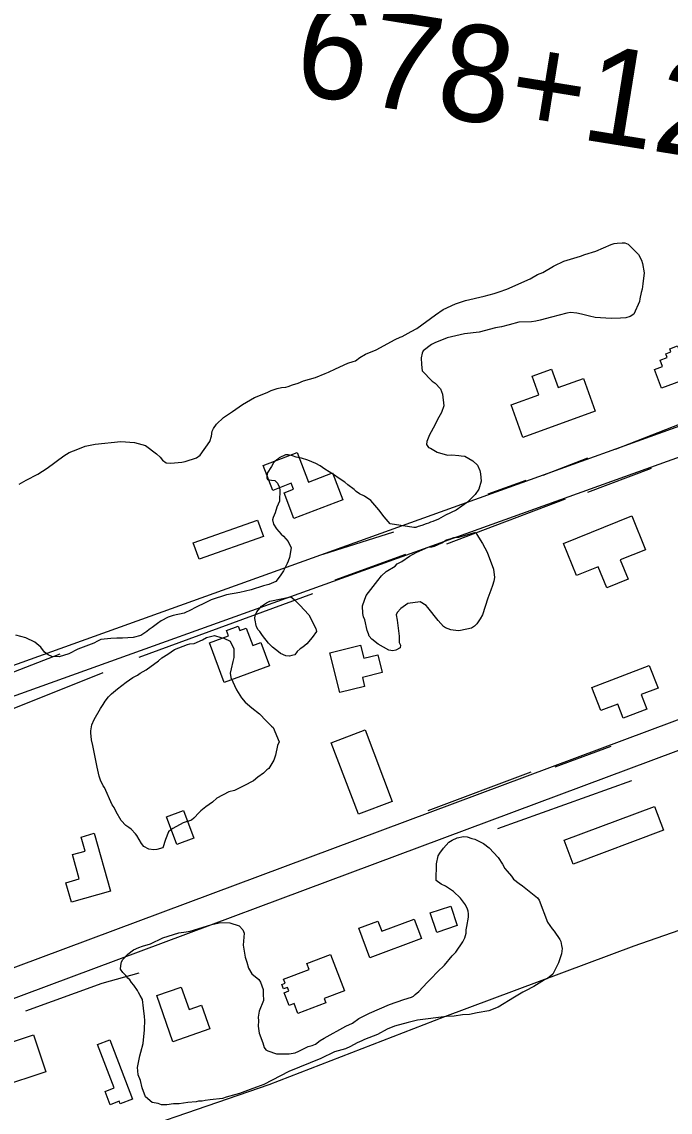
# Model space of a CAD drawing. Extents: x 3161564 to 3199464, y 849354 to 874788.
# Drawn here: x 3173329 to 3173999, y 861534 to 862661 of the extents above; entities that cross this region are included whole.
import ezdxf

# ---------------------------------------------------------------- set-up
doc = ezdxf.new("R2010")
doc.units = 0
for name, color, linetype in [('V-BLDG-OTLN', 7, 'Continuous'), ('V-ROAD-CNTR', 7, 'Continuous'), ('V-SITE-VEGE', 7, 'Continuous'), ('V-SURV-IDEN', 7, 'Continuous'), ('V-TOPO-SHOR', 7, 'Continuous')]:
    doc.layers.add(name, color=color, linetype=linetype)

msp = doc.modelspace()

# ---------------------------------------------------------------- linework, layer by layer
at = {"layer": 'V-BLDG-OTLN'}
for points in [[(3173989.6, 862281.9), (3173982.5, 862301.3), (3173990.6, 862304.3), (3173988.2, 862310.9), (3173995.6, 862313.6), (3173994.2, 862317.5), (3173999.5, 862319.5), (3173998.3, 862322.6), (3174006.3, 862325.6), (3174009.2, 862318), (3174044.6, 862331.1), (3174054, 862305.8)], [(3173834.3, 862264.7), (3173863, 862275.1), (3173856, 862294.3), (3173876.1, 862301.6), (3173883, 862282.7), (3173909, 862292.1), (3173921.2, 862258.3), (3173846.5, 862231.1)], [(3173609.9, 862147.2), (3173599.8, 862173.6), (3173609.7, 862177.4), (3173607.3, 862183.7), (3173588.1, 862176.3), (3173578.3, 862201.9), (3173613.4, 862215.4), (3173625.2, 862184.9), (3173649.7, 862194.4), (3173660.4, 862166.6)], [(3173902, 862088.2), (3173888.5, 862121.4), (3173959, 862150.1), (3173973.3, 862115), (3173947.2, 862104.4), (3173955.3, 862084.4), (3173933.2, 862075.4), (3173924.3, 862097.3)], [(3173572.5, 862145.6), (3173578.5, 862128.6), (3173512.1, 862105.2), (3173506.1, 862122.2)], [(3173537.8, 861977.7), (3173522.7, 862018.8), (3173542.3, 862026.1), (3173540.2, 862031.6), (3173552.3, 862036.1), (3173554, 862031.5), (3173560.7, 862033.9), (3173567.4, 862015.8), (3173575.9, 862018.9), (3173584.7, 861995)], [(3173657.5, 861967.3), (3173647.1, 862008.3), (3173678.9, 862016.4), (3173682.3, 862002.8), (3173696.6, 862006.4), (3173701.3, 861988), (3173680.7, 861982.8), (3173683, 861973.7)], [(3173927.1, 861948.7), (3173917.9, 861972.7), (3173977.1, 861995.4), (3173986.2, 861971.8), (3173968.9, 861965.2), (3173974.7, 861950), (3173950.2, 861940.7), (3173944.5, 861955.4)], [(3173676.6, 861841.5), (3173648.6, 861915.5), (3173683.7, 861928.7), (3173711.6, 861854.7)], [(3173489.1, 861810.3), (3173478.5, 861839), (3173496.1, 861845.5), (3173506.7, 861816.8)], [(3173898.4, 861789.9), (3173889.1, 861814.6), (3173982.6, 861849.6), (3173991.9, 861824.9)], [(3173380.1, 861750.8), (3173374.5, 861770.8), (3173388.2, 861774.6), (3173381.3, 861799.8), (3173394.2, 861803.4), (3173390.2, 861818), (3173403.8, 861821.8), (3173420.4, 861762)], [(3173750.9, 861739.5), (3173772, 861746.5), (3173778.7, 861726.4), (3173757.6, 861719.4)], [(3173688.4, 861693.1), (3173676.9, 861723.6), (3173696.8, 861731), (3173700.7, 861720.5), (3173734.3, 861733.1), (3173741.8, 861713.2)], [(3173599.3, 861671), (3173625.6, 861681), (3173623.2, 861687.2), (3173647.7, 861696.5), (3173662.1, 861658.9), (3173641.4, 861651), (3173643.1, 861646.6), (3173614, 861635.5), (3173610.1, 861645.8), (3173605, 861643.8), (3173599.9, 861657), (3173604.8, 861658.9), (3173603.4, 861662.6), (3173599.3, 861661), (3173597.5, 861665.6), (3173600.9, 861666.9)], [(3173468.3, 861654), (3173493.6, 861662.8), (3173501.7, 861639.6), (3173514.6, 861644.1), (3173523.2, 861619.6), (3173484.9, 861606.2)], [(3173305.6, 861559.3), (3173292.8, 861597.5), (3173341, 861613.6), (3173353.8, 861575.4)], [(3173419.8, 861608.4), (3173443.3, 861547), (3173430.5, 861542.1), (3173429.5, 861544.9), (3173420.2, 861541.3), (3173414.9, 861555), (3173424.2, 861558.6), (3173407.1, 861603.6)]]:
    msp.add_lwpolyline(points, close=True, dxfattribs=at)
at = {"layer": 'V-ROAD-CNTR'}
for points in [[(3174370.7, 862373), (3172595.4, 861734.8)], [(3174380.8, 862344.8), (3172605.6, 861706.6)], [(3172696.1, 861449.9), (3174403, 862087.4)], [(3172706.5, 861421.8), (3174413.5, 862059.3)]]:
    msp.add_lwpolyline(points, dxfattribs=at)
at = {"layer": 'V-SITE-VEGE'}
for points in [[(3173345.3, 862192.9), (3173355.1, 862199.4), (3173372.3, 862212.1), (3173378, 862215.4), (3173386.9, 862218.9), (3173394.4, 862222.1), (3173404.8, 862224.2), (3173431.2, 862226.7), (3173445.3, 862225.7), (3173456.7, 862222.6), (3173468.1, 862214.2), (3173471.7, 862210.5), (3173474.3, 862207.5), (3173477.9, 862204.8), (3173482.7, 862204.3), (3173494.3, 862205.6), (3173497.6, 862206.3), (3173509.5, 862209.8), (3173513.3, 862212.7), (3173523.2, 862226.7), (3173524.8, 862232.2), (3173525.6, 862237.4), (3173527.1, 862240.3), (3173530.2, 862244.7), (3173537.3, 862251.7), (3173546.7, 862257.8), (3173550.1, 862260.3), (3173556.8, 862265.1), (3173569.2, 862272.3), (3173575.5, 862274.8), (3173583, 862278), (3173586.4, 862279.4), (3173592.7, 862281.5), (3173597.2, 862282.6), (3173601.6, 862282.9), (3173604.2, 862283.6), (3173608.7, 862285.3), (3173614.3, 862287.1), (3173619.9, 862289.6), (3173632.2, 862293.1), (3173642.3, 862297), (3173645.7, 862298.4), (3173653.1, 862302), (3173665.8, 862307.8), (3173671.1, 862309.5), (3173673.7, 862310.2), (3173678.2, 862313.8), (3173683.8, 862317.1), (3173695, 862321.7), (3173714.5, 862332.2), (3173719.7, 862334.7), (3173721.9, 862335.4), (3173731.3, 862340.4), (3173736.9, 862343.7), (3173756.1, 862357.8), (3173764.3, 862363.2), (3173777, 862369), (3173787.1, 862372.5), (3173806.5, 862377), (3173816.9, 862379.8), (3173822.1, 862381.6), (3173829.9, 862384.4), (3173854.2, 862395.1), (3173861.7, 862399.4), (3173867.3, 862401.6), (3173878.2, 862408.1), (3173881.6, 862409.9), (3173886, 862411.7), (3173888.7, 862413.1), (3173906.2, 862418.4), (3173910.7, 862420.1), (3173921.8, 862423.7), (3173929.7, 862426.9), (3173937.9, 862430.5), (3173940.9, 862431.5), (3173943.9, 862431.8), (3173949.1, 862432.1), (3173952, 862432.1), (3173955.3, 862430.9)], [(3173955.3, 862430.9), (3173965.9, 862420), (3173969.2, 862414.4), (3173970.2, 862411), (3173971.9, 862401.3), (3173970.6, 862389.8), (3173969.8, 862384.3), (3173968.6, 862381), (3173967.4, 862374.3), (3173967, 862371.4), (3173961.2, 862358.5), (3173957.4, 862355.9), (3173953, 862354.5), (3173947.4, 862354.3), (3173937.7, 862354), (3173921.1, 862355.1), (3173915.5, 862356.3), (3173907, 862358.6), (3173902.2, 862359.5), (3173895.9, 862360.3), (3173891.8, 862359.6), (3173876.2, 862355.4), (3173864.3, 862352.3), (3173859.8, 862351.3), (3173855.3, 862350.6), (3173842.4, 862350.1), (3173832.3, 862347.6), (3173824.5, 862345.5), (3173818.1, 862344.2), (3173801.4, 862340), (3173786.1, 862338), (3173768.3, 862333.9), (3173755.6, 862328.9), (3173752.2, 862327.1), (3173743.6, 862320.6), (3173742.4, 862318), (3173741.6, 862313.2), (3173741.9, 862306.5), (3173742.5, 862299.8), (3173752.7, 862289.2), (3173756, 862287), (3173761.5, 862281.3), (3173763.6, 862275.7), (3173764.9, 862263.8), (3173762.5, 862256.8), (3173758.3, 862249.5), (3173755.6, 862243.6), (3173749.9, 862233.7), (3173747.2, 862226.7), (3173746.8, 862223.7), (3173749, 862220.7), (3173751.2, 862219.9), (3173758.1, 862215.7), (3173768.5, 862212.6), (3173773.3, 862212.9), (3173780.4, 862212.4), (3173782.9, 862212), (3173786.6, 862211.5), (3173794.7, 862206.9), (3173799.8, 862202.4), (3173802, 862196.8), (3173802.7, 862193.5), (3173803.6, 862186), (3173800.9, 862177.5), (3173797.1, 862172), (3173794.8, 862169.5), (3173789.2, 862164), (3173777.6, 862156), (3173766.7, 862150.7), (3173759.2, 862146.7), (3173753.6, 862144.2), (3173751, 862143.5), (3173749.1, 862142.4), (3173746.5, 862141.7), (3173742.1, 862139.9), (3173738.3, 862138.9), (3173736.1, 862137.8), (3173733.9, 862137.9), (3173709.4, 862141.6), (3173703.3, 862148.8), (3173697.8, 862156.3), (3173689.4, 862165.7), (3173682.8, 862170.2), (3173677.7, 862172.9), (3173674.4, 862175.2), (3173672.2, 862177.1), (3173665.6, 862182), (3173662.7, 862184.7), (3173656.8, 862188.5), (3173650.9, 862192.6), (3173641.8, 862198.4), (3173637, 862201.8), (3173632.6, 862204.1), (3173624.5, 862207.6), (3173617.8, 862209.5), (3173612.3, 862210.7), (3173608.6, 862211.9), (3173604.2, 862213.1), (3173601.2, 862213.1), (3173594.9, 862209.9), (3173593.3, 862208.4)], [(3173593.3, 862208.4), (3173590.7, 862206.6), (3173588.8, 862204.8), (3173586.9, 862201.1), (3173582.4, 862194.2), (3173581.9, 862189.3), (3173582.6, 862187.5), (3173586.7, 862186.7), (3173590.4, 862186.6), (3173592.9, 862183.6), (3173594.7, 862179.9), (3173595.4, 862176.9), (3173595.2, 862165), (3173593.7, 862162.1), (3173592.5, 862159.1), (3173590.6, 862153.2), (3173588.6, 862148.4), (3173587.9, 862145.8), (3173588.9, 862141.4), (3173592.1, 862136.5), (3173596.9, 862130.9), (3173599.4, 862129), (3173604.2, 862123.3), (3173607, 862117), (3173605.4, 862107), (3173604.2, 862103.3), (3173603.1, 862100.7), (3173599.2, 862093), (3173596.6, 862089), (3173593.9, 862085.3), (3173591.2, 862082), (3173584.1, 862079.1), (3173578.6, 862077.8), (3173565.9, 862073.5), (3173554, 862070.7), (3173540.2, 862068.4), (3173524.5, 862063.1), (3173519.7, 862060.6), (3173507.7, 862054.8), (3173504, 862052.7), (3173496.5, 862049.4), (3173485.3, 862047), (3173480.1, 862045.3), (3173473, 862041.3), (3173469.2, 862038.8), (3173463.6, 862034.4), (3173460.6, 862032.6), (3173458, 862030.4), (3173452, 862026.4), (3173443.8, 862024.4), (3173433, 862023.4), (3173427.1, 862023.5), (3173420.8, 862023.3), (3173410.7, 862022.3), (3173407, 862020.5), (3173403.3, 862018.4), (3173386.8, 862012), (3173377.5, 862007.3), (3173367.4, 862004.1), (3173360, 862004.6), (3173356.3, 862006.2), (3173352.3, 862009.2), (3173348.7, 862014.1), (3173342.4, 862019.4), (3173332.9, 862024), (3173322.9, 862026.7)], [(3173326.2, 862182.8), (3173333.4, 862186.8), (3173345.3, 862192.9)], [(3173558.5, 861718.7), (3173557.6, 861706.1), (3173559.6, 861693.8), (3173561.3, 861688.6), (3173563.1, 861682.3), (3173566.7, 861676.6), (3173573.6, 861670.6), (3173575.5, 861668), (3173578.3, 861660.5), (3173578.2, 861656), (3173578.5, 861649), (3173574.2, 861637.9), (3173573, 861631.6), (3173573.3, 861627.9), (3173573.2, 861622.4), (3173574.2, 861615.3), (3173577.8, 861605.2), (3173579.2, 861600.4), (3173581, 861598.1), (3173583.2, 861597), (3173592, 861593.9), (3173605, 861593.7), (3173611.3, 861595), (3173615.1, 861596.5), (3173624.8, 861601.5), (3173628.9, 861602.5), (3173632.3, 861604), (3173637.1, 861607.6), (3173641.3, 861610.1), (3173663.7, 861622.4), (3173670.5, 861625.6), (3173677.2, 861630.3), (3173688.1, 861636), (3173708.6, 861645), (3173723.5, 861649.9), (3173731.4, 861652.4), (3173733.6, 861653.5), (3173735.1, 861655.3), (3173738.9, 861658.2), (3173747.6, 861667.7), (3173751.7, 861671.7), (3173758.5, 861678.6), (3173765.7, 861685.6), (3173773.6, 861695.1), (3173777.4, 861699.1), (3173784.6, 861709.7), (3173786.5, 861713.8), (3173788.1, 861718.6), (3173788.1, 861721.9), (3173788.6, 861725.6), (3173790.2, 861735.2), (3173790.3, 861738.6), (3173789.9, 861741.2), (3173789.2, 861743.4), (3173787.1, 861747.9), (3173785.3, 861750.5), (3173782, 861754.7), (3173774.7, 861761.5), (3173766.6, 861767.2), (3173762.2, 861769.4), (3173757.1, 861772.9), (3173757.4, 861790.3), (3173759, 861798.4), (3173760.9, 861801.4), (3173764.7, 861806.5), (3173770, 861812.7), (3173773.4, 861814.9), (3173778.6, 861817), (3173785.3, 861818.4), (3173789, 861818.3), (3173793.8, 861816.4), (3173796.8, 861815.6), (3173806, 861811.4), (3173811.8, 861806.8), (3173820.9, 861796.7), (3173825.6, 861789.9), (3173827.8, 861785.4), (3173830.3, 861782.8), (3173834.7, 861777.5), (3173836.9, 861774.5), (3173842.7, 861770), (3173846, 861767.7), (3173861.8, 861755.2)], [(3173861.8, 861755.2), (3173863.2, 861752.6), (3173872.1, 861729.8), (3173876.8, 861723), (3173879, 861720.8), (3173884.8, 861712.1), (3173885.9, 861709.9), (3173886.5, 861705.8), (3173887.2, 861702.8), (3173886.4, 861697.3), (3173883.3, 861688.1), (3173881.7, 861684.4), (3173877.5, 861676.3), (3173871.9, 861671.9), (3173868.9, 861670.5), (3173858, 861663.6), (3173849.4, 861659), (3173846.4, 861657.5), (3173837.8, 861652.5), (3173820.9, 861642), (3173811.2, 861638.4), (3173799.3, 861636.4), (3173791.5, 861634.7), (3173784.1, 861634.1), (3173775.5, 861632.7), (3173767.7, 861632.5), (3173737.6, 861628.5), (3173728, 861626.1), (3173713.8, 861622.3), (3173706.3, 861619.4), (3173696.2, 861614), (3173682.8, 861608.7), (3173680.2, 861607.2), (3173675.3, 861605.1), (3173668.6, 861601.5), (3173663.3, 861599), (3173651.8, 861595.8), (3173637.9, 861589), (3173604.7, 861575.5), (3173578.9, 861562.2), (3173567.7, 861557.9), (3173553.9, 861553), (3173540.1, 861549.1), (3173536.4, 861547.7), (3173523.4, 861546.4), (3173518.2, 861545.8), (3173515.2, 861545.1), (3173511.5, 861544.8), (3173508.9, 861544.1), (3173500.3, 861543.5), (3173491.4, 861542.1), (3173485.5, 861542.2), (3173478.8, 861541.2), (3173473.2, 861541.3), (3173469.9, 861542.5), (3173463.6, 861543.7), (3173456.7, 861549.4), (3173453.1, 861558.7), (3173451.4, 861566.2), (3173449.2, 861572.1), (3173448.6, 861576.2), (3173448.3, 861579.9), (3173449.9, 861586.6), (3173450.7, 861591.8), (3173451.9, 861595.5), (3173454.2, 861604.7), (3173455.6, 861618.8), (3173455.6, 861621.7), (3173456.1, 861625.8), (3173456.1, 861628.4), (3173455.8, 861632.5), (3173454.5, 861641), (3173453.5, 861650), (3173451.3, 861654.1), (3173449.5, 861657.1), (3173448.5, 861659.3), (3173444.5, 861664.9), (3173442.3, 861667.6), (3173440.5, 861670.2), (3173438.3, 861672.1), (3173436.5, 861674.7), (3173433.2, 861678.1), (3173431, 861681.5), (3173431.1, 861685.2), (3173431.9, 861688.9), (3173433.1, 861691.5), (3173438.3, 861696.9), (3173444.3, 861701.3), (3173449.9, 861703.8), (3173453.7, 861705.2), (3173461.9, 861707.7), (3173474.6, 861713.8), (3173491, 861719.1), (3173498.8, 861720), (3173502.9, 861720.7), (3173525.3, 861727.4), (3173534.6, 861729.5), (3173543.8, 861729.3), (3173553.4, 861726.2), (3173557.1, 861722), (3173558.5, 861718.7)]]:
    msp.add_lwpolyline(points, dxfattribs=at)
for points in [[(3173797.9, 862133.1), (3173799, 862130.8), (3173804.8, 862121.5), (3173809.8, 862112.5), (3173816.2, 862094.9), (3173817.2, 862086.4), (3173816.4, 862082.3), (3173815.2, 862077.9), (3173813.3, 862073.1), (3173810.5, 862065), (3173804.7, 862047.7), (3173802.4, 862043.6), (3173799, 862038.5), (3173796.7, 862035.9), (3173793.3, 862033.8), (3173782.2, 862031.3), (3173779.6, 862031), (3173772.2, 862032.3), (3173766.6, 862034.2), (3173764.4, 862035.7), (3173759, 862041.7), (3173748.4, 862055.3), (3173746.6, 862057.2), (3173740.4, 862061), (3173727.7, 862059.3), (3173720.6, 862054.3), (3173716.8, 862050.2), (3173715.7, 862047.7), (3173716.7, 862042.1), (3173718.6, 862025.7), (3173718.9, 862021.3), (3173718.9, 862019), (3173720, 862016.4), (3173719.6, 862013.5), (3173715.4, 862011.3), (3173712.1, 862010.6), (3173708, 862011.1), (3173697, 862017.2), (3173690.4, 862022.5), (3173687.9, 862025.5), (3173687.2, 862028.1), (3173685.7, 862031.5), (3173683.3, 862042.6), (3173681.9, 862045.6), (3173681.2, 862049), (3173681, 862056.8), (3173684.8, 862067.5), (3173696.6, 862083.2), (3173700.4, 862088), (3173705.3, 862092.3), (3173714.7, 862098.1), (3173716.5, 862100.3), (3173721.4, 862102.8), (3173729.3, 862108.3), (3173737.1, 862112.6), (3173748.7, 862117.6), (3173752.4, 862117.9), (3173755.1, 862118.6), (3173762.9, 862122.2), (3173767.8, 862125.1), (3173771.5, 862126.1), (3173775.2, 862127.5), (3173780.4, 862127.8)], [(3173606.9, 862066.2), (3173609.9, 862063.9), (3173616.1, 862057.8), (3173625.5, 862047.7), (3173632.7, 862033.5), (3173633.4, 862030.5), (3173628.9, 862024.3), (3173623.2, 862017.7), (3173619.1, 862014.4), (3173616.4, 862012.6), (3173613.4, 862009.7), (3173610.8, 862006.4), (3173607.8, 862005.7), (3173605.5, 862005), (3173601.5, 862005.4), (3173596.3, 862007.7), (3173594.1, 862009.3), (3173587.9, 862014.2), (3173583.9, 862018.3), (3173577.7, 862026.2), (3173576.3, 862028.5), (3173574.8, 862030.3), (3173573, 862032.2), (3173571.2, 862035.2), (3173570.5, 862038.2), (3173570.2, 862040.4), (3173569.8, 862043.8), (3173569.9, 862047.1), (3173571.8, 862050.8), (3173576.4, 862056.6), (3173581.6, 862059.9), (3173585, 862061.7)], [(3173594.8, 861916.5), (3173593.2, 861912.5), (3173590.9, 861902.5), (3173589.3, 861897.3), (3173584, 861888.9), (3173582.1, 861887.4), (3173578.7, 861884.1), (3173572.7, 861879.8), (3173568.2, 861876.2), (3173558.1, 861870.8), (3173551.3, 861867.5), (3173548.7, 861866.1), (3173542.8, 861864.7), (3173530.4, 861858.2), (3173525.9, 861853.9), (3173519.1, 861849.2), (3173513.9, 861845.2), (3173512, 861843.3), (3173506.7, 861837.5), (3173504.1, 861835.3), (3173495.5, 861832.5), (3173485, 861826.7), (3173482.8, 861825.3), (3173480.5, 861823.5), (3173477.4, 861815.4), (3173474.7, 861806.9), (3173468.3, 861805.1), (3173465.4, 861804.8), (3173460.2, 861805.3), (3173455, 861808.3), (3173452.5, 861811.3), (3173447.8, 861819.6), (3173446.3, 861821.4), (3173442, 861826), (3173439.4, 861827.9), (3173436.5, 861829.8), (3173431.7, 861835), (3173426.3, 861844), (3173424.2, 861848.5), (3173422.4, 861851.1), (3173414.5, 861869.1), (3173413, 861870.9), (3173410.2, 861876.6), (3173408.8, 861881), (3173406.7, 861890.3), (3173402.2, 861912.7), (3173400.8, 861918.6), (3173400.2, 861925.7), (3173400.3, 861927.9), (3173401.1, 861933.8), (3173403.8, 861939.3), (3173410.3, 861950.7), (3173412.9, 861954.8), (3173414.9, 861958.4), (3173418.3, 861962.8), (3173421.7, 861966.1), (3173427.7, 861971.2), (3173436.7, 861978.1), (3173440.1, 861980.3), (3173443.5, 861982.8), (3173448.3, 861985.3), (3173451.3, 861987.5), (3173457.3, 861990.8), (3173470.1, 862000.2), (3173473.5, 862003.1), (3173479.8, 862007.1), (3173486.6, 862011.8), (3173500, 862017.1), (3173502.6, 862017.8), (3173507.1, 862018.1), (3173515.7, 862021.7), (3173519.8, 862024.2), (3173528, 862026.3), (3173534.6, 862024.3), (3173537.6, 862023.5), (3173544.2, 862020.5), (3173547.8, 862012.6), (3173548.1, 862006.7), (3173548, 862003.7), (3173546.8, 861999.3), (3173545.2, 861991.9), (3173544.1, 861987.5), (3173544.7, 861983), (3173550.8, 861970.3), (3173555.9, 861961.7), (3173559.5, 861957.5), (3173566.4, 861951.5), (3173574.5, 861945.4), (3173581.4, 861938.2), (3173586.9, 861932.6), (3173588.7, 861931.1)]]:
    msp.add_lwpolyline(points, close=True, dxfattribs=at)
at = {"layer": 'V-TOPO-SHOR'}
for p, q in [((3173942.2, 862218.9), (3174032.8, 862254.4)), ((3173867.6, 862192.2), (3173913.8, 862210)), ((3173913.8, 862174.5), (3173979.5, 862199.3)), ((3173810.8, 862172.7), (3173849.8, 862186.9)), ((3173768.1, 862121.2), (3173890.7, 862167.4)), ((3173640.2, 862110.5), (3173713.1, 862133.6)), ((3173652.7, 862083.9), (3173725.5, 862110.5)), ((3173450.2, 862003.9), (3173629.6, 862069.7)), ((3173286.7, 861975.5), (3173368.4, 862007.5)), ((3173297.4, 861941.8), (3173412.9, 861987.9)), ((3173880, 861890.7), (3173937.8, 861912)), ((3173748.6, 861845.4), (3173855.2, 861885.4)), ((3173820.5, 861826.7), (3173959.1, 861876.5))]:
    msp.add_line(p, q, dxfattribs=at)
for points in [[(3174406, 861871.4), (3174192.2, 861792.9), (3174158.3, 861782.3), (3174134.3, 861772), (3174108.3, 861762.9), (3174079.9, 861752.2), (3174039.2, 861732.4), (3173961, 861705.2), (3173765.5, 861632), (3173584, 861561.9), (3173381.9, 861492.2), (3173201.4, 861423.7), (3173075.9, 861372.5), (3172901.4, 861302.3), (3172810.1, 861261.7), (3172801.9, 861259)], [(3173332.9, 861638.4), (3173412, 861666.9), (3173450.2, 861677.5)]]:
    msp.add_lwpolyline(points, dxfattribs=at)

# ---------------------------------------------------------------- texts
at = {"layer": 'V-SURV-IDEN'}
msp.add_text('678+12.0', height=100, rotation=350.8376, dxfattribs=at).set_placement((3173607.1, 862587.6))

doc.saveas('drawing.dxf')
